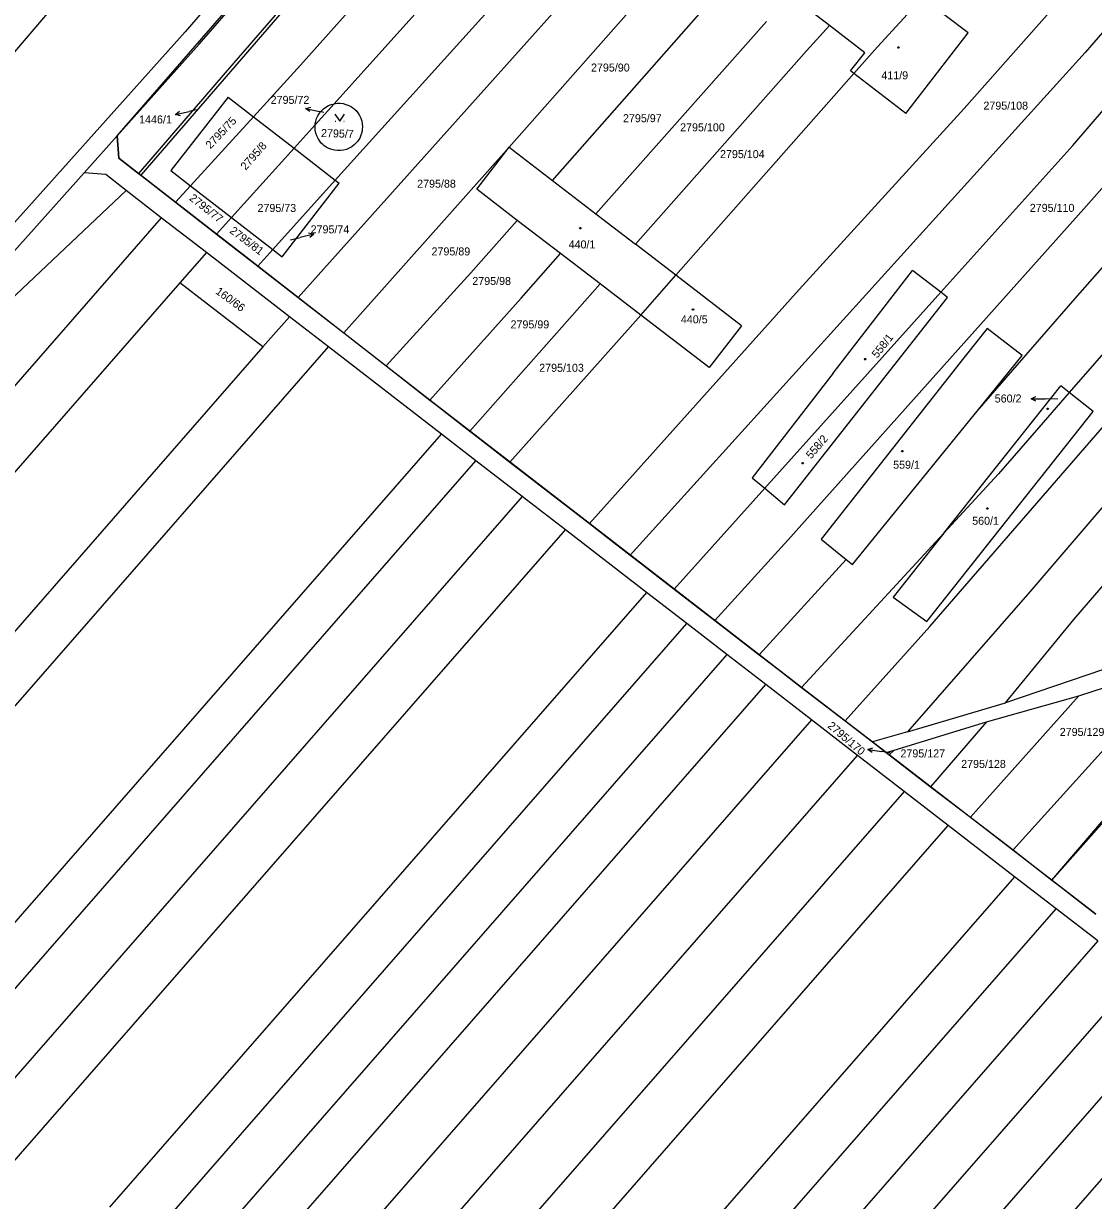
# Model space of a CAD drawing. Extents: x -580630 to -576196, y -1189024 to -1183567.
# Drawn here: x -579205 to -578977.9, y -1186322.7 to -1186072.7 of the extents above; entities that cross this region are included whole.
import ezdxf

# ---------------------------------------------------------------- set-up
doc = ezdxf.new("R2010")
doc.units = 0
for name, color, linetype in [('Vrstva 1', 7, 'Continuous'), ('Vrstva 16', 7, 'Continuous'), ('Vrstva 18', 7, 'Continuous'), ('Vrstva 19', 7, 'Continuous'), ('Vrstva 25', 7, 'Continuous'), ('Vrstva 6', 7, 'Continuous'), ('Vrstva 63', 7, 'Continuous')]:
    doc.layers.add(name, color=color, linetype=linetype)

msp = doc.modelspace()

# ---------------------------------------------------------------- linework, layer by layer
at = {"layer": 'Vrstva 1'}
for p, q in [((-579398.1, -1186301.88), (-578990.93, -1185826.58)), ((-578979.05, -1185852.8), (-579170.73, -1186074.45)), ((-579167.73, -1186077.09), (-578979.81, -1185859.79)), ((-579102.25, -1186013.96), (-579162.21, -1186083.17)), ((-579143.98, -1186063.03), (-579180.14, -1186104.89)), ((-579033.92, -1186073.12), (-579042.32, -1186066.61)), ((-579004.47, -1186074.69), (-579014.22, -1186067.2)), ((-579170.73, -1186074.45), (-579281.58, -1186198.32)), ((-579026.41, -1186078.94), (-579033.92, -1186073.12)), ((-579017.72, -1186091.8), (-579004.47, -1186074.69)), ((-579185.15, -1186096.56), (-579167.73, -1186077.09)), ((-579029.41, -1186082.75), (-579026.41, -1186078.94)), ((-579162.21, -1186083.17), (-579180.59, -1186104.54)), ((-579028.72, -1186083.29), (-579029.41, -1186082.75)), ((-579017.72, -1186091.8), (-579028.72, -1186083.29)), ((-579161.6, -1186088.3), (-579173.75, -1186103.92)), ((-579161.6, -1186088.3), (-579156.2, -1186092.49)), ((-579140.27, -1186090.12), (-579139.68, -1186089.88)), ((-579139.68, -1186089.88), (-579139.06, -1186089.72)), ((-579139.06, -1186089.72), (-579138.44, -1186089.64)), ((-579138.44, -1186089.64), (-579137.8, -1186089.63)), ((-579137.8, -1186089.63), (-579137.17, -1186089.71)), ((-579137.17, -1186089.71), (-579136.56, -1186089.87)), ((-579136.56, -1186089.87), (-579135.97, -1186090.1)), ((-579156.2, -1186092.49), (-579147.58, -1186099.17)), ((-579142.79, -1186092.85), (-579142.53, -1186092.27)), ((-579142.53, -1186092.27), (-579142.19, -1186091.73)), ((-579142.19, -1186091.73), (-579141.95, -1186091.42)), ((-579141.95, -1186091.42), (-579141.79, -1186091.24)), ((-579141.79, -1186091.24), (-579141.33, -1186090.8)), ((-579141.33, -1186090.8), (-579140.82, -1186090.43)), ((-579140.82, -1186090.43), (-579140.27, -1186090.12)), ((-579135.97, -1186090.1), (-579135.41, -1186090.4)), ((-579135.41, -1186090.4), (-579135.13, -1186090.59)), ((-579135.13, -1186090.59), (-579134.89, -1186090.77)), ((-579134.89, -1186090.77), (-579134.43, -1186091.2)), ((-579134.43, -1186091.2), (-579134.03, -1186091.69)), ((-579134.03, -1186091.69), (-579133.68, -1186092.23)), ((-579133.68, -1186092.23), (-579133.41, -1186092.8)), ((-579143.13, -1186094.71), (-579143.11, -1186094.2)), ((-579143.09, -1186095.34), (-579143.13, -1186094.71)), ((-579143.11, -1186094.2), (-579143.1, -1186094.08)), ((-579143.1, -1186094.08), (-579142.98, -1186093.45)), ((-579142.98, -1186093.45), (-579142.79, -1186092.85)), ((-579133.41, -1186092.8), (-579133.22, -1186093.41)), ((-579133.22, -1186093.41), (-579133.1, -1186094.03)), ((-579133.1, -1186094.03), (-579133.06, -1186094.66)), ((-579133.06, -1186094.66), (-579133.09, -1186095.2)), ((-579192.18, -1186104.42), (-579185.15, -1186096.56)), ((-579185.15, -1186096.56), (-579184.78, -1186101.29)), ((-579142.96, -1186095.96), (-579143.09, -1186095.34)), ((-579142.76, -1186096.57), (-579142.96, -1186095.96)), ((-579142.48, -1186097.14), (-579142.76, -1186096.57)), ((-579142.14, -1186097.67), (-579142.48, -1186097.14)), ((-579133.64, -1186097.01), (-579133.97, -1186097.55)), ((-579133.38, -1186096.43), (-579133.64, -1186097.01)), ((-579133.19, -1186095.82), (-579133.38, -1186096.43)), ((-579133.09, -1186095.2), (-579133.19, -1186095.82)), ((-579147.58, -1186099.17), (-579138.83, -1186105.95)), ((-579141.73, -1186098.15), (-579142.14, -1186097.67)), ((-579141.51, -1186098.39), (-579141.73, -1186098.15)), ((-579141.26, -1186098.58), (-579141.51, -1186098.39)), ((-579140.74, -1186098.95), (-579141.26, -1186098.58)), ((-579140.18, -1186099.25), (-579140.74, -1186098.95)), ((-579139.59, -1186099.47), (-579140.18, -1186099.25)), ((-579138.97, -1186099.62), (-579139.59, -1186099.47)), ((-579138.34, -1186099.69), (-579138.97, -1186099.62)), ((-579137.71, -1186099.68), (-579138.34, -1186099.69)), ((-579137.08, -1186099.59), (-579137.71, -1186099.68)), ((-579136.46, -1186099.43), (-579137.08, -1186099.59)), ((-579135.88, -1186099.19), (-579136.46, -1186099.43)), ((-579135.33, -1186098.87), (-579135.88, -1186099.19)), ((-579134.82, -1186098.49), (-579135.33, -1186098.87)), ((-579134.37, -1186098.05), (-579134.82, -1186098.49)), ((-579134.1, -1186097.73), (-579134.37, -1186098.05)), ((-579133.97, -1186097.55), (-579134.1, -1186097.73)), ((-579108.81, -1186107.87), (-579101.92, -1186098.99)), ((-579101.92, -1186098.99), (-579092.73, -1186106.04)), ((-579184.78, -1186101.29), (-579180.59, -1186104.54)), ((-579192.18, -1186104.42), (-579278.57, -1186200.95)), ((-579187.57, -1186104.73), (-579192.18, -1186104.42)), ((-579183.26, -1186108.16), (-579187.57, -1186104.73)), ((-579180.59, -1186104.54), (-579180.14, -1186104.89)), ((-579180.14, -1186104.89), (-579172.77, -1186110.63)), ((-579173.75, -1186103.92), (-579169.59, -1186107.15)), ((-579169.59, -1186107.15), (-579160.85, -1186113.92)), ((-579150.1, -1186122.24), (-579137.98, -1186106.6)), ((-579138.83, -1186105.95), (-579137.98, -1186106.6)), ((-579092.73, -1186106.04), (-579083.52, -1186113.11)), ((-579183.26, -1186108.16), (-579221.85, -1186144.69)), ((-579175.79, -1186113.94), (-579183.26, -1186108.16)), ((-579100.18, -1186114.5), (-579108.81, -1186107.87)), ((-579172.77, -1186110.63), (-579164.02, -1186117.44)), ((-579175.79, -1186113.94), (-579344.17, -1186306.81)), ((-579166.21, -1186121.33), (-579175.79, -1186113.94)), ((-579160.85, -1186113.92), (-579152.12, -1186120.68)), ((-579091, -1186121.54), (-579100.18, -1186114.5)), ((-579083.52, -1186113.11), (-579075.1, -1186119.57)), ((-579164.02, -1186117.44), (-579155.31, -1186124.22)), ((-579066.5, -1186126.16), (-579075.1, -1186119.57)), ((-579166.21, -1186121.33), (-579171.83, -1186127.76)), ((-579148.56, -1186134.97), (-579166.21, -1186121.33)), ((-579152.12, -1186120.68), (-579150.1, -1186122.24)), ((-579082.57, -1186128.01), (-579091, -1186121.54)), ((-579155.31, -1186124.22), (-579146.71, -1186130.91)), ((-579052.59, -1186136.91), (-579066.5, -1186126.16)), ((-579033.11, -1186146.97), (-579016.25, -1186125.18)), ((-579010.26, -1186129.78), (-579016.25, -1186125.18)), ((-579171.83, -1186127.76), (-579330.1, -1186309.04)), ((-579154.18, -1186141.4), (-579171.83, -1186127.76)), ((-579073.95, -1186134.62), (-579082.57, -1186128.01)), ((-579008.82, -1186130.88), (-579010.26, -1186129.78)), ((-579146.71, -1186130.91), (-579137.05, -1186138.43)), ((-579043.43, -1186174.96), (-579008.82, -1186130.88)), ((-579148.56, -1186134.97), (-579154.18, -1186141.4)), ((-579140.26, -1186141.39), (-579148.56, -1186134.97)), ((-579059.44, -1186145.76), (-579073.95, -1186134.62)), ((-579052.59, -1186136.91), (-579059.44, -1186145.76)), ((-579000.43, -1186137.45), (-579005.35, -1186143.7)), ((-578993.02, -1186143.23), (-579000.43, -1186137.45)), ((-579137.05, -1186138.43), (-579128.05, -1186145.43)), ((-579154.18, -1186141.4), (-579302.96, -1186311.82)), ((-579291.81, -1186314.97), (-579140.26, -1186141.39)), ((-579116.31, -1186159.89), (-579140.26, -1186141.39)), ((-579005.35, -1186143.7), (-579035.67, -1186182.21)), ((-579002.57, -1186155), (-578993.02, -1186143.23)), ((-579128.05, -1186145.43), (-579118.74, -1186152.67)), ((-579033.11, -1186146.97), (-579050.29, -1186169.18)), ((-579009.62, -1186180.95), (-578984.78, -1186149.68)), ((-578983.01, -1186151.08), (-578984.78, -1186149.68)), ((-578977.94, -1186155.08), (-578983.01, -1186151.08)), ((-579118.74, -1186152.67), (-579117.32, -1186153.77)), ((-579117.32, -1186153.77), (-579110.25, -1186159.28)), ((-579029.04, -1186187.64), (-579002.57, -1186155)), ((-579013.24, -1186199.69), (-578977.94, -1186155.08)), ((-579478.92, -1186575.23), (-579116.31, -1186159.89)), ((-579108.96, -1186165.58), (-579116.31, -1186159.89)), ((-579110.25, -1186159.28), (-579108.79, -1186160.41)), ((-579108.79, -1186160.41), (-579101.75, -1186165.86)), ((-579242.14, -1186318.13), (-579108.96, -1186165.58)), ((-579099.14, -1186173.16), (-579108.96, -1186165.58)), ((-579101.75, -1186165.86), (-579084.86, -1186178.91)), ((-579050.29, -1186169.18), (-579047.63, -1186171.42)), ((-579047.63, -1186171.42), (-579043.43, -1186174.96)), ((-579099.14, -1186173.16), (-579227.13, -1186319.76)), ((-579089.98, -1186180.24), (-579099.14, -1186173.16)), ((-579084.86, -1186178.91), (-579081.62, -1186181.42)), ((-579213.1, -1186321.27), (-579089.98, -1186180.24)), ((-579072.75, -1186193.55), (-579089.98, -1186180.24)), ((-579081.62, -1186181.42), (-579076.22, -1186185.59)), ((-579035.67, -1186182.21), (-579030.38, -1186186.54)), ((-579009.62, -1186180.95), (-579020.41, -1186194.54)), ((-579076.22, -1186185.59), (-579075.35, -1186186.26)), ((-579075.35, -1186186.26), (-579066.85, -1186192.84)), ((-579030.38, -1186186.54), (-579029.04, -1186187.64)), ((-579072.75, -1186193.55), (-579186.75, -1186324.12)), ((-579064.19, -1186200.17), (-579072.75, -1186193.55)), ((-579066.85, -1186192.84), (-579058.22, -1186199.51)), ((-579020.41, -1186194.54), (-579013.24, -1186199.69)), ((-579058.22, -1186199.51), (-579048.82, -1186206.77)), ((-579173.64, -1186325.54), (-579064.19, -1186200.17)), ((-579055.7, -1186206.72), (-579064.19, -1186200.17)), ((-578986.66, -1186254.66), (-578942.07, -1186202.26)), ((-579055.7, -1186206.72), (-579160.66, -1186326.94)), ((-579047.45, -1186213.09), (-579055.7, -1186206.72)), ((-579048.82, -1186206.77), (-579044.74, -1186209.92)), ((-579044.74, -1186209.92), (-579039.82, -1186213.71)), ((-579148.04, -1186328.3), (-579047.45, -1186213.09)), ((-579037.75, -1186220.59), (-579047.45, -1186213.09)), ((-579039.82, -1186213.71), (-579030.58, -1186220.81)), ((-579037.75, -1186220.59), (-579133.17, -1186329.9)), ((-579027.95, -1186228.17), (-579037.75, -1186220.59)), ((-579030.58, -1186220.81), (-579024.77, -1186225.29)), ((-579024.77, -1186225.29), (-579021.86, -1186227.53)), ((-579118.17, -1186331.51), (-579027.95, -1186228.17)), ((-579018.06, -1186235.81), (-579027.95, -1186228.17)), ((-579021.86, -1186227.53), (-579021.22, -1186228.02)), ((-579021.22, -1186228.02), (-579012.46, -1186234.81)), ((-579012.46, -1186234.81), (-579003.97, -1186241.3)), ((-579018.06, -1186235.81), (-579103.03, -1186333.14)), ((-579008.7, -1186243.04), (-579018.06, -1186235.81)), ((-579003.97, -1186241.3), (-578994.94, -1186248.25)), ((-579088.71, -1186334.68), (-579008.7, -1186243.04)), ((-578994.61, -1186253.92), (-579008.7, -1186243.04)), ((-578994.94, -1186248.25), (-578986.66, -1186254.66)), ((-578994.61, -1186253.92), (-579067.14, -1186336.99)), ((-578985.79, -1186260.74), (-578994.61, -1186253.92)), ((-578986.66, -1186254.66), (-578984.99, -1186255.95)), ((-578984.99, -1186255.95), (-578980.81, -1186259.19)), ((-578980.81, -1186259.19), (-578977.38, -1186261.85)), ((-579053.63, -1186338.44), (-578985.79, -1186260.74)), ((-578976.94, -1186267.58), (-578985.79, -1186260.74)), ((-578976.94, -1186267.58), (-579040.08, -1186339.9)), ((-579026.43, -1186341.37), (-578968.02, -1186274.47)), ((-579012.88, -1186342.83), (-578959.17, -1186281.31)), ((-578950.11, -1186288.31), (-578999.01, -1186344.32))]:
    msp.add_line(p, q, dxfattribs=at)
at = {"layer": 'Vrstva 16'}
for p, q in [((-579172.75, -1186092.047), (-579169.83, -1186091.36)), ((-579168.35, -1186091.01), (-579169.83, -1186091.36)), ((-579145.138, -1186090.709), (-579142.21, -1186091.36)), ((-579141.26, -1186091.58), (-579142.21, -1186091.36)), ((-579143.406, -1186117.435), (-579146.32, -1186118.15)), ((-579148.32, -1186118.64), (-579146.32, -1186118.15)), ((-578991.08, -1186152.402), (-578988.08, -1186152.44)), ((-578985.42, -1186152.47), (-578988.08, -1186152.44)), ((-579025.728, -1186226.914), (-579022.76, -1186227.35)), ((-579021.1, -1186227.59), (-579022.76, -1186227.35))]:
    msp.add_line(p, q, dxfattribs=at)
for points in [[(-579171.662, -1186092.305), (-579172.75, -1186092.047), (-579171.891, -1186091.332)], [(-579144.271, -1186091.414), (-579145.138, -1186090.709), (-579144.054, -1186090.438)], [(-579144.497, -1186117.188), (-579143.406, -1186117.435), (-579144.258, -1186118.159)], [(-578990.086, -1186152.914), (-578991.08, -1186152.402), (-578990.073, -1186151.914)], [(-579024.811, -1186227.554), (-579025.728, -1186226.914), (-579024.666, -1186226.565)]]:
    msp.add_lwpolyline(points, dxfattribs=at)
at = {"layer": 'Vrstva 25'}
for p, q in [((-579138.85, -1186093.45), (-579138.75, -1186093.45)), ((-579137.05, -1186093.45), (-579136.95, -1186093.45))]:
    msp.add_line(p, q, dxfattribs=at)
for points in [[(-579019.17, -1186077.66), (-579019.08, -1186077.81), (-579019.17, -1186077.96), (-579019.35, -1186077.96), (-579019.44, -1186077.81), (-579019.35, -1186077.66)], [(-579086.72, -1186116), (-579086.63, -1186116.15), (-579086.72, -1186116.3), (-579086.9, -1186116.3), (-579086.99, -1186116.15), (-579086.9, -1186116)], [(-579062.78, -1186133.31), (-579062.69, -1186133.46), (-579062.78, -1186133.61), (-579062.96, -1186133.61), (-579063.05, -1186133.46), (-579062.96, -1186133.31)], [(-579026.24, -1186143.86), (-579026.15, -1186144.01), (-579026.24, -1186144.16), (-579026.42, -1186144.16), (-579026.51, -1186144.01), (-579026.42, -1186143.86)], [(-578987.48, -1186154.37), (-578987.39, -1186154.52), (-578987.48, -1186154.67), (-578987.66, -1186154.67), (-578987.75, -1186154.52), (-578987.66, -1186154.37)], [(-579018.35, -1186163.37), (-579018.26, -1186163.52), (-579018.35, -1186163.67), (-579018.53, -1186163.67), (-579018.62, -1186163.52), (-579018.53, -1186163.37)], [(-579039.49, -1186165.93), (-579039.4, -1186166.08), (-579039.49, -1186166.23), (-579039.67, -1186166.23), (-579039.76, -1186166.08), (-579039.67, -1186165.93)], [(-579000.28, -1186175.54), (-579000.19, -1186175.69), (-579000.28, -1186175.84), (-579000.46, -1186175.84), (-579000.55, -1186175.69), (-579000.46, -1186175.54)]]:
    msp.add_lwpolyline(points, close=True, dxfattribs=at)
msp.add_lwpolyline([(-579138.9, -1186091.95), (-579137.9, -1186093.45), (-579136.9, -1186091.95)], dxfattribs=at)
at = {"layer": 'Vrstva 6'}
for p, q in [((-578925.3, -1186015.81), (-578979.63, -1186078.87)), ((-578982.25, -1186098.57), (-578916.79, -1186022.54)), ((-579084.29, -1186028.83), (-579139.06, -1186089.72)), ((-579005.3, -1186090.77), (-578966.94, -1186047.25)), ((-578929.14, -1186054.27), (-578979.87, -1186112.08)), ((-579064.02, -1186056.07), (-579101.92, -1186098.99)), ((-579146.71, -1186130.91), (-579082.14, -1186058.74)), ((-579138.83, -1186105.95), (-579095.52, -1186057.95)), ((-579092.73, -1186106.04), (-579055.73, -1186064)), ((-579023.71, -1186077.61), (-579014.22, -1186067.2)), ((-579146.22, -1186081.56), (-579133.74, -1186067.53)), ((-579083.52, -1186113.11), (-579047.31, -1186072.27)), ((-579033.92, -1186073.12), (-579038.75, -1186078.51)), ((-578917.53, -1186075.59), (-578983.01, -1186151.08)), ((-578979.63, -1186078.87), (-579076.22, -1186185.59)), ((-579038.75, -1186078.51), (-579075.1, -1186119.57)), ((-579028.72, -1186083.29), (-579023.71, -1186077.61)), ((-579156.2, -1186092.49), (-579146.22, -1186081.56)), ((-579066.5, -1186126.16), (-579028.72, -1186083.29)), ((-579139.06, -1186089.72), (-579143.11, -1186094.2)), ((-579169.59, -1186107.15), (-579156.2, -1186092.49)), ((-579040.37, -1186129.2), (-579005.3, -1186090.77)), ((-579143.11, -1186094.2), (-579147.58, -1186099.17)), ((-578981.77, -1186131.08), (-578951.1, -1186096.42)), ((-579147.58, -1186099.17), (-579160.85, -1186113.92)), ((-579101.92, -1186098.99), (-579137.05, -1186138.43)), ((-579010.26, -1186129.78), (-578982.25, -1186098.57)), ((-579172.77, -1186110.63), (-579169.59, -1186107.15)), ((-579152.12, -1186120.68), (-579138.83, -1186105.95)), ((-578979.87, -1186112.08), (-579042.74, -1186182.46)), ((-579160.85, -1186113.92), (-579164.02, -1186117.44)), ((-579110.02, -1186125.68), (-579100.18, -1186114.5)), ((-579155.31, -1186124.22), (-579152.12, -1186120.68)), ((-579099.4, -1186131.02), (-579091, -1186121.54)), ((-579128.05, -1186145.43), (-579110.02, -1186125.68)), ((-579073.95, -1186134.62), (-579066.5, -1186126.16)), ((-579082.57, -1186128.01), (-579110.25, -1186159.28)), ((-579084.86, -1186178.91), (-579040.37, -1186129.2)), ((-579047.63, -1186171.42), (-579010.26, -1186129.78)), ((-579118.74, -1186152.67), (-579099.4, -1186131.02)), ((-579002.57, -1186155), (-578981.77, -1186131.08)), ((-579076.22, -1186137.2), (-579073.95, -1186134.62)), ((-579012.58, -1186200.78), (-578953.67, -1186132.72)), ((-579101.75, -1186165.86), (-579076.22, -1186137.2)), ((-578941.78, -1186135.31), (-578991.34, -1186193.42)), ((-578982.05, -1186199.27), (-578936.89, -1186146.87)), ((-578983.01, -1186151.08), (-578988.52, -1186157.43)), ((-578988.52, -1186157.43), (-578997.99, -1186168.34)), ((-578997.99, -1186168.34), (-579009.62, -1186180.95)), ((-579066.85, -1186192.84), (-579047.63, -1186171.42)), ((-579042.74, -1186182.46), (-579058.22, -1186199.51)), ((-579009.62, -1186180.95), (-579039.82, -1186213.71)), ((-579048.82, -1186206.77), (-579030.38, -1186186.54)), ((-578991.34, -1186193.42), (-579017.31, -1186223.15)), ((-578996.52, -1186217), (-578982.05, -1186199.27)), ((-579030.58, -1186220.81), (-579012.58, -1186200.78)), ((-578975.72, -1186209.94), (-578996.52, -1186217)), ((-578958.71, -1186208.14), (-578994.94, -1186248.25)), ((-578980.97, -1186215.52), (-578958.71, -1186208.14)), ((-579017.31, -1186223.15), (-578996.52, -1186217)), ((-578980.97, -1186215.52), (-579003.97, -1186241.3)), ((-579000.55, -1186221.03), (-578980.97, -1186215.52)), ((-579020.15, -1186227.01), (-579000.55, -1186221.03)), ((-579000.55, -1186221.03), (-579012.46, -1186234.81)), ((-578986.66, -1186254.66), (-578956.21, -1186220.13)), ((-579017.31, -1186223.15), (-579024.77, -1186225.29)), ((-579021.86, -1186227.53), (-579020.15, -1186227.01)), ((-579020.15, -1186227.01), (-579021.22, -1186228.02))]:
    msp.add_line(p, q, dxfattribs=at)
at = {"layer": 'Vrstva 63'}
for p, q in [((-579185.15, -1186096.56), (-579073.77, -1185968.44)), ((-579184.78, -1186101.29), (-579185.15, -1186096.56)), ((-579180.59, -1186104.54), (-579184.78, -1186101.29)), ((-579155.31, -1186124.22), (-579180.59, -1186104.54)), ((-579118.74, -1186152.67), (-579155.31, -1186124.22)), ((-579084.86, -1186178.91), (-579118.74, -1186152.67)), ((-579039.82, -1186213.71), (-579084.86, -1186178.91)), ((-579021.86, -1186227.53), (-579039.82, -1186213.71)), ((-578977.38, -1186261.85), (-579021.86, -1186227.53))]:
    msp.add_line(p, q, dxfattribs=at)

# ---------------------------------------------------------------- texts
at = {"layer": 'Vrstva 16'}
for s, p in [('2795/72', (-579152.556, -1186089.76)), ('1446/1', (-579180.486, -1186093.92)), ('2795/74', (-579144.072, -1186117.26)), ('560/2', (-578998.82, -1186153.19))]:
    msp.add_text(s, height=1.7, dxfattribs=at).set_placement(p)
msp.add_text('2795/170', height=1.7, rotation=319.42397, dxfattribs=at).set_placement((-579034.445, -1186222.095))
at = {"layer": 'Vrstva 18'}
for s, height, p in [('2795/90', 1.7, (-579084.539, -1186082.89)), ('2795/108', 1.7, (-579001.22, -1186090.98)), ('1446/1', 0.1, (-579168.552, -1186091.01)), ('2795/72', 0.1, (-579141.55, -1186091.58)), ('2795/97', 1.7, (-579077.752, -1186093.65)), ('2795/100', 1.7, (-579065.617, -1186095.59)), ('2795/104', 1.7, (-579057.15, -1186101.28)), ('2795/88', 1.7, (-579121.449, -1186107.57)), ('2795/73', 1.7, (-579155.349, -1186112.72)), ('2795/110', 1.7, (-578991.382, -1186112.7)), ('2795/74', 0.1, (-579148.605, -1186118.64)), ('2795/89', 1.7, (-579118.399, -1186121.95)), ('2795/98', 1.7, (-579109.742, -1186128.23)), ('2795/99', 1.7, (-579101.622, -1186137.45)), ('2795/103', 1.7, (-579095.537, -1186146.67)), ('2795/129', 1.7, (-578985.017, -1186224.02)), ('2795/170', 0.1, (-579021.407, -1186227.59)), ('2795/127', 1.7, (-579018.837, -1186228.58)), ('2795/128', 1.7, (-579005.947, -1186230.82))]:
    msp.add_text(s, height=height, dxfattribs=at).set_placement(p)
for s, rotation, p in [('2795/75', 46.46688, (-579165.314, -1186099.442)), ('2795/7', 358.27051, (-579141.881, -1186096.794)), ('2795/8', 48.52952, (-579157.847, -1186103.964)), ('2795/77', 321.83039, (-579169.973, -1186110.056)), ('2795/81', 322.74713, (-579161.388, -1186117.013)), ('160/66', 323.83574, (-579164.399, -1186129.927))]:
    msp.add_text(s, height=1.7, rotation=rotation, dxfattribs=at).set_placement(p)
at = {"layer": 'Vrstva 19'}
for s, height, p in [('411/9', 1.7, (-579022.897, -1186084.55)), ('440/1', 1.7, (-579089.292, -1186120.46)), ('440/5', 1.7, (-579065.457, -1186136.37)), ('560/2', 0.1, (-578985.631, -1186152.47)), ('559/1', 1.7, (-579020.389, -1186167.26)), ('560/1', 1.7, (-579003.609, -1186179.17))]:
    msp.add_text(s, height=height, dxfattribs=at).set_placement(p)
for s, rotation, p in [('558/1', 51.90998, (-579023.748, -1186143.893)), ('558/2', 49.38896, (-579037.801, -1186165.304))]:
    msp.add_text(s, height=1.7, rotation=rotation, dxfattribs=at).set_placement(p)

doc.saveas('drawing.dxf')
